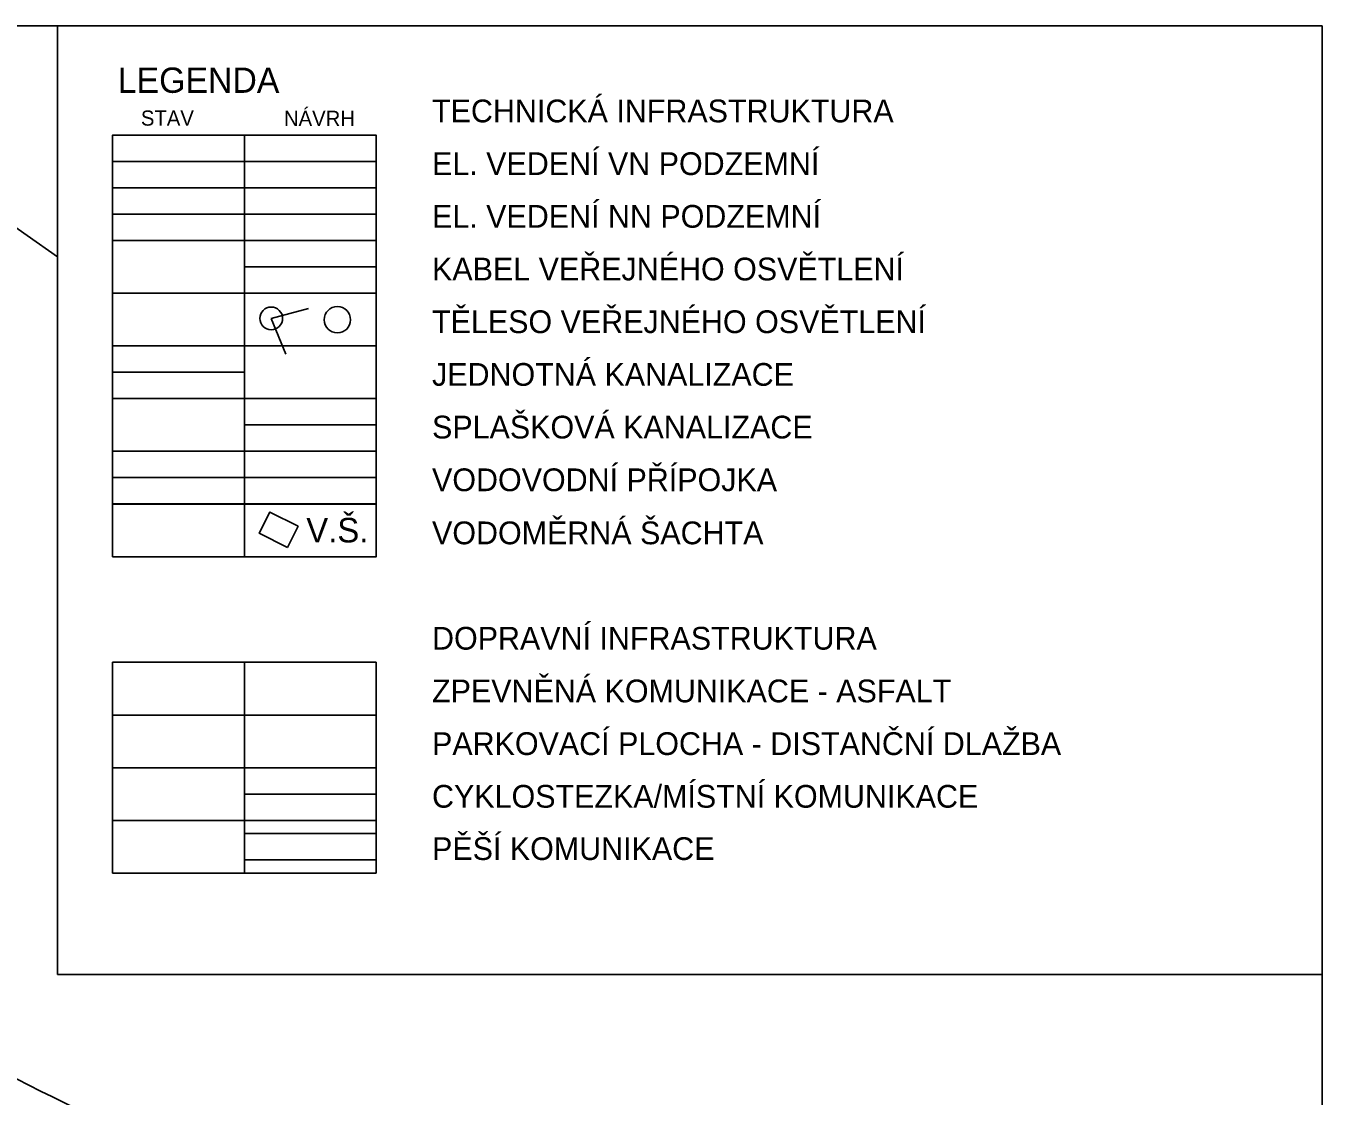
# Model space of a CAD drawing. Extents: x -504998 to -504814, y -1117353 to -1117234.
# Drawn here: x -504875.37 to -504826.17, y -1117277.64 to -1117237.02 of the extents above; entities that cross this region are included whole.
import ezdxf

# ---------------------------------------------------------------- set-up
doc = ezdxf.new("R2010")
doc.units = 0
for name, color, linetype in [('01_ST tenká', 7, 'Continuous'), ('02_PL_PARKOVISTE', 7, 'Continuous'), ('03_razitko', 7, 'Continuous'), ('_01_CYKLOSTEZKA', 7, 'Continuous'), ('_01_kanalizace', 7, 'Continuous'), ('_01_vedeni_NN_nadzemni', 7, 'Continuous'), ('_01_vedeni_VN_podzemni', 7, 'Continuous'), ('_01_vedeni_VN_podzemni_NAVRH', 7, 'Continuous'), ('_01_VO', 7, 'Continuous'), ('_01_vodovod_pripojky', 7, 'Continuous'), ('_02_pl_ cesta', 7, 'Continuous'), ('Hranice parcel', 7, 'Continuous'), ('pop-ram-popis', 7, 'Continuous')]:
    doc.layers.add(name, color=color, linetype=linetype)

msp = doc.modelspace()

# ---------------------------------------------------------------- linework, layer by layer
at = {"layer": '01_ST tenká'}
for p, q in [((-504867.08, -1117267.675), (-504862.08, -1117267.675)), ((-504867.08, -1117267.675), (-504862.08, -1117267.675)), ((-504867.08, -1117268.675), (-504862.08, -1117268.675)), ((-504867.08, -1117268.675), (-504862.08, -1117268.675))]:
    msp.add_line(p, q, dxfattribs=at)
msp.add_open_spline([(-504884.688, -1117272.271), (-504882.067, -1117273.747), (-504872.833, -1117278.571), (-504857.22, -1117285.84), (-504840.071, -1117292.154), (-504829.913, -1117296.084), (-504826.17, -1117297.542)], degree=3, dxfattribs=at)
at = {"layer": '02_PL_PARKOVISTE'}
msp.add_lwpolyline([(-504867.08, -1117265.175), (-504862.08, -1117265.175), (-504862.08, -1117263.175), (-504867.08, -1117263.175)], close=True, dxfattribs=at)
msp.add_lwpolyline([(-504867.08, -1117265.175), (-504862.08, -1117265.175), (-504862.08, -1117263.175), (-504867.08, -1117263.175)], close=True, dxfattribs=at)
at = {"layer": '_01_CYKLOSTEZKA'}
msp.add_line((-504867.08, -1117266.175), (-504862.08, -1117266.175), dxfattribs=at)
msp.add_line((-504867.08, -1117266.175), (-504862.08, -1117266.175), dxfattribs=at)
at = {"layer": '_01_kanalizace'}
for p, q in [((-504872.08, -1117250.16), (-504867.08, -1117250.16)), ((-504872.08, -1117250.16), (-504867.08, -1117250.16)), ((-504867.08, -1117252.16), (-504862.08, -1117252.16)), ((-504867.08, -1117252.16), (-504862.08, -1117252.16))]:
    msp.add_line(p, q, dxfattribs=at)
at = {"layer": '_01_vedeni_NN_nadzemni'}
msp.add_line((-504872.08, -1117244.16), (-504867.08, -1117244.16), dxfattribs=at)
msp.add_line((-504872.08, -1117244.16), (-504867.08, -1117244.16), dxfattribs=at)
at = {"layer": '_01_vedeni_VN_podzemni'}
msp.add_line((-504872.08, -1117242.16), (-504867.08, -1117242.16), dxfattribs=at)
msp.add_line((-504872.08, -1117242.16), (-504867.08, -1117242.16), dxfattribs=at)
at = {"layer": '_01_vedeni_VN_podzemni_NAVRH'}
for p, q in [((-504867.08, -1117242.16), (-504862.08, -1117242.16)), ((-504867.08, -1117242.16), (-504862.08, -1117242.16)), ((-504867.08, -1117244.16), (-504862.08, -1117244.16)), ((-504867.08, -1117244.16), (-504862.08, -1117244.16))]:
    msp.add_line(p, q, dxfattribs=at)
at = {"layer": '_01_VO'}
for p, q in [((-504867.08, -1117246.16), (-504862.08, -1117246.16)), ((-504867.08, -1117246.16), (-504862.08, -1117246.16)), ((-504864.642, -1117247.744), (-504866.06, -1117248.12)), ((-504864.642, -1117247.744), (-504866.06, -1117248.12)), ((-504865.51, -1117249.48), (-504866.06, -1117248.12)), ((-504865.51, -1117249.48), (-504866.06, -1117248.12))]:
    msp.add_line(p, q, dxfattribs=at)
for centre, radius in [((-504866.06, -1117248.12), 0.43), ((-504866.06, -1117248.12), 0.43), ((-504863.55, -1117248.17), 0.5), ((-504863.55, -1117248.17), 0.5)]:
    msp.add_circle(centre, radius, dxfattribs=at)
at = {"layer": '_01_vodovod_pripojky'}
for p, q in [((-504872.08, -1117254.16), (-504867.08, -1117254.16)), ((-504872.08, -1117254.16), (-504867.08, -1117254.16)), ((-504867.08, -1117254.16), (-504862.08, -1117254.16)), ((-504867.08, -1117254.16), (-504862.08, -1117254.16))]:
    msp.add_line(p, q, dxfattribs=at)
msp.add_lwpolyline([(-504865.441, -1117256.812), (-504865.039, -1117256.008), (-504866.112, -1117255.471), (-504866.515, -1117256.276)], close=True, dxfattribs=at)
msp.add_lwpolyline([(-504865.441, -1117256.812), (-504865.039, -1117256.008), (-504866.112, -1117255.471), (-504866.515, -1117256.276)], close=True, dxfattribs=at)
at = {"layer": '_02_pl_ cesta'}
for points in [[(-504867.08, -1117263.175), (-504862.08, -1117263.175), (-504862.08, -1117261.175), (-504867.08, -1117261.175)], [(-504867.08, -1117263.175), (-504862.08, -1117263.175), (-504862.08, -1117261.175), (-504867.08, -1117261.175)], [(-504867.08, -1117267.175), (-504862.08, -1117267.175), (-504862.08, -1117265.175), (-504867.08, -1117265.175)], [(-504867.08, -1117267.175), (-504862.08, -1117267.175), (-504862.08, -1117265.175), (-504867.08, -1117265.175)], [(-504867.08, -1117267.675), (-504862.08, -1117267.675), (-504862.08, -1117268.675), (-504867.08, -1117268.675)], [(-504867.08, -1117267.675), (-504862.08, -1117267.675), (-504862.08, -1117268.675), (-504867.08, -1117268.675)]]:
    msp.add_lwpolyline(points, close=True, dxfattribs=at)
at = {"layer": 'Hranice parcel'}
msp.add_line((-504874.17, -1117245.785), (-504886.671, -1117237.019), dxfattribs=at)
at = {"layer": 'pop-ram-popis'}
for points in [[(-504985.829, -1117237.019), (-504826.17, -1117237.019), (-504826.17, -1117339.419), (-504985.829, -1117339.419)], [(-504826.17, -1117339.419), (-504826.17, -1117273.019), (-504874.17, -1117273.019), (-504874.17, -1117237.019), (-504985.829, -1117237.019), (-504985.829, -1117339.419)], [(-504826.17, -1117339.419), (-504826.17, -1117237.019), (-504985.829, -1117237.019), (-504985.829, -1117339.419)], [(-504826.17, -1117273.019), (-504874.17, -1117273.019), (-504874.17, -1117237.019), (-504985.829, -1117237.019), (-504985.829, -1117339.419), (-504826.17, -1117339.419)], [(-504826.17, -1117237.019), (-504874.17, -1117237.019), (-504874.17, -1117273.019), (-504826.17, -1117273.019)], [(-504826.17, -1117273.019), (-504826.17, -1117237.019), (-504874.17, -1117237.019), (-504874.17, -1117273.019)], [(-504872.08, -1117243.16), (-504867.08, -1117243.16), (-504867.08, -1117241.16), (-504872.08, -1117241.16)], [(-504872.08, -1117243.16), (-504867.08, -1117243.16), (-504867.08, -1117241.16), (-504872.08, -1117241.16)], [(-504867.08, -1117243.16), (-504862.08, -1117243.16), (-504862.08, -1117241.16), (-504867.08, -1117241.16)], [(-504867.08, -1117243.16), (-504862.08, -1117243.16), (-504862.08, -1117241.16), (-504867.08, -1117241.16)], [(-504872.08, -1117245.16), (-504867.08, -1117245.16), (-504867.08, -1117243.16), (-504872.08, -1117243.16)], [(-504872.08, -1117245.16), (-504867.08, -1117245.16), (-504867.08, -1117243.16), (-504872.08, -1117243.16)], [(-504867.08, -1117245.16), (-504862.08, -1117245.16), (-504862.08, -1117243.16), (-504867.08, -1117243.16)], [(-504867.08, -1117245.16), (-504862.08, -1117245.16), (-504862.08, -1117243.16), (-504867.08, -1117243.16)], [(-504872.08, -1117247.16), (-504867.08, -1117247.16), (-504867.08, -1117245.16), (-504872.08, -1117245.16)], [(-504872.08, -1117247.16), (-504867.08, -1117247.16), (-504867.08, -1117245.16), (-504872.08, -1117245.16)], [(-504867.08, -1117247.16), (-504862.08, -1117247.16), (-504862.08, -1117245.16), (-504867.08, -1117245.16)], [(-504867.08, -1117247.16), (-504862.08, -1117247.16), (-504862.08, -1117245.16), (-504867.08, -1117245.16)], [(-504872.08, -1117249.16), (-504867.08, -1117249.16), (-504867.08, -1117247.16), (-504872.08, -1117247.16)], [(-504872.08, -1117249.16), (-504867.08, -1117249.16), (-504867.08, -1117247.16), (-504872.08, -1117247.16)], [(-504867.08, -1117249.16), (-504862.08, -1117249.16), (-504862.08, -1117247.16), (-504867.08, -1117247.16)], [(-504867.08, -1117249.16), (-504862.08, -1117249.16), (-504862.08, -1117247.16), (-504867.08, -1117247.16)], [(-504872.08, -1117251.16), (-504867.08, -1117251.16), (-504867.08, -1117249.16), (-504872.08, -1117249.16)], [(-504872.08, -1117251.16), (-504867.08, -1117251.16), (-504867.08, -1117249.16), (-504872.08, -1117249.16)], [(-504867.08, -1117251.16), (-504862.08, -1117251.16), (-504862.08, -1117249.16), (-504867.08, -1117249.16)], [(-504867.08, -1117251.16), (-504862.08, -1117251.16), (-504862.08, -1117249.16), (-504867.08, -1117249.16)], [(-504872.08, -1117253.16), (-504867.08, -1117253.16), (-504867.08, -1117251.16), (-504872.08, -1117251.16)], [(-504872.08, -1117253.16), (-504867.08, -1117253.16), (-504867.08, -1117251.16), (-504872.08, -1117251.16)], [(-504867.08, -1117253.16), (-504862.08, -1117253.16), (-504862.08, -1117251.16), (-504867.08, -1117251.16)], [(-504867.08, -1117253.16), (-504862.08, -1117253.16), (-504862.08, -1117251.16), (-504867.08, -1117251.16)], [(-504872.08, -1117255.16), (-504867.08, -1117255.16), (-504867.08, -1117253.16), (-504872.08, -1117253.16)], [(-504872.08, -1117255.16), (-504867.08, -1117255.16), (-504867.08, -1117253.16), (-504872.08, -1117253.16)], [(-504867.08, -1117255.16), (-504862.08, -1117255.16), (-504862.08, -1117253.16), (-504867.08, -1117253.16)], [(-504867.08, -1117255.16), (-504862.08, -1117255.16), (-504862.08, -1117253.16), (-504867.08, -1117253.16)], [(-504872.08, -1117257.175), (-504867.08, -1117257.175), (-504867.08, -1117255.175), (-504872.08, -1117255.175)], [(-504872.08, -1117257.175), (-504867.08, -1117257.175), (-504867.08, -1117255.175), (-504872.08, -1117255.175)], [(-504867.08, -1117257.175), (-504862.08, -1117257.175), (-504862.08, -1117255.175), (-504867.08, -1117255.175)], [(-504867.08, -1117257.175), (-504862.08, -1117257.175), (-504862.08, -1117255.175), (-504867.08, -1117255.175)], [(-504872.08, -1117263.175), (-504867.08, -1117263.175), (-504867.08, -1117261.175), (-504872.08, -1117261.175)], [(-504872.08, -1117263.175), (-504867.08, -1117263.175), (-504867.08, -1117261.175), (-504872.08, -1117261.175)], [(-504867.08, -1117263.175), (-504862.08, -1117263.175), (-504862.08, -1117261.175), (-504867.08, -1117261.175)], [(-504867.08, -1117263.175), (-504862.08, -1117263.175), (-504862.08, -1117261.175), (-504867.08, -1117261.175)], [(-504872.08, -1117265.175), (-504867.08, -1117265.175), (-504867.08, -1117263.175), (-504872.08, -1117263.175)], [(-504872.08, -1117265.175), (-504867.08, -1117265.175), (-504867.08, -1117263.175), (-504872.08, -1117263.175)], [(-504867.08, -1117265.175), (-504862.08, -1117265.175), (-504862.08, -1117263.175), (-504867.08, -1117263.175)], [(-504867.08, -1117265.175), (-504862.08, -1117265.175), (-504862.08, -1117263.175), (-504867.08, -1117263.175)], [(-504872.08, -1117267.175), (-504867.08, -1117267.175), (-504867.08, -1117265.175), (-504872.08, -1117265.175)], [(-504872.08, -1117267.175), (-504867.08, -1117267.175), (-504867.08, -1117265.175), (-504872.08, -1117265.175)], [(-504867.08, -1117267.175), (-504862.08, -1117267.175), (-504862.08, -1117265.175), (-504867.08, -1117265.175)], [(-504867.08, -1117267.175), (-504862.08, -1117267.175), (-504862.08, -1117265.175), (-504867.08, -1117265.175)], [(-504872.08, -1117269.175), (-504867.08, -1117269.175), (-504867.08, -1117267.175), (-504872.08, -1117267.175)], [(-504872.08, -1117269.175), (-504867.08, -1117269.175), (-504867.08, -1117267.175), (-504872.08, -1117267.175)], [(-504867.08, -1117269.175), (-504862.08, -1117269.175), (-504862.08, -1117267.175), (-504867.08, -1117267.175)], [(-504867.08, -1117269.175), (-504862.08, -1117269.175), (-504862.08, -1117267.175), (-504867.08, -1117267.175)]]:
    msp.add_lwpolyline(points, close=True, dxfattribs=at)

# ---------------------------------------------------------------- texts
at = {"layer": '03_razitko'}
for s, height, p in [('LEGENDA', 0.96, (-504871.886, -1117239.559)), ('LEGENDA', 0.96, (-504871.886, -1117239.559)), ('TECHNICKÁ INFRASTRUKTURA', 0.864, (-504859.956, -1117240.679)), ('TECHNICKÁ INFRASTRUKTURA', 0.864, (-504859.956, -1117240.679)), ('STAV', 0.576, (-504871.008, -1117240.805)), ('STAV', 0.576, (-504871.008, -1117240.805)), ('NÁVRH', 0.576, (-504865.578, -1117240.815)), ('NÁVRH', 0.576, (-504865.578, -1117240.815)), ('EL. VEDENÍ VN PODZEMNÍ', 0.864, (-504859.956, -1117242.679)), ('EL. VEDENÍ VN PODZEMNÍ', 0.864, (-504859.956, -1117242.679)), ('EL. VEDENÍ NN PODZEMNÍ', 0.864, (-504859.956, -1117244.679)), ('EL. VEDENÍ NN PODZEMNÍ', 0.864, (-504859.956, -1117244.679)), ('KABEL VEŘEJNÉHO OSVĚTLENÍ', 0.864, (-504859.956, -1117246.679)), ('KABEL VEŘEJNÉHO OSVĚTLENÍ', 0.864, (-504859.956, -1117246.679)), ('TĚLESO VEŘEJNÉHO OSVĚTLENÍ', 0.864, (-504859.956, -1117248.679)), ('TĚLESO VEŘEJNÉHO OSVĚTLENÍ', 0.864, (-504859.956, -1117248.679)), ('JEDNOTNÁ KANALIZACE', 0.864, (-504859.956, -1117250.679)), ('JEDNOTNÁ KANALIZACE', 0.864, (-504859.956, -1117250.679)), ('SPLAŠKOVÁ KANALIZACE', 0.864, (-504859.956, -1117252.679)), ('SPLAŠKOVÁ KANALIZACE', 0.864, (-504859.956, -1117252.679)), ('VODOVODNÍ PŘÍPOJKA', 0.864, (-504859.956, -1117254.679)), ('VODOVODNÍ PŘÍPOJKA', 0.864, (-504859.956, -1117254.679)), ('VODOMĚRNÁ ŠACHTA', 0.864, (-504859.956, -1117256.694)), ('VODOMĚRNÁ ŠACHTA', 0.864, (-504859.956, -1117256.694)), ('DOPRAVNÍ INFRASTRUKTURA', 0.864, (-504859.956, -1117260.694)), ('DOPRAVNÍ INFRASTRUKTURA', 0.864, (-504859.956, -1117260.694)), ('ZPEVNĚNÁ KOMUNIKACE - ASFALT', 0.864, (-504859.956, -1117262.694)), ('ZPEVNĚNÁ KOMUNIKACE - ASFALT', 0.864, (-504859.956, -1117262.694)), ('PARKOVACÍ PLOCHA - DISTANČNÍ DLAŽBA', 0.864, (-504859.956, -1117264.694)), ('PARKOVACÍ PLOCHA - DISTANČNÍ DLAŽBA', 0.864, (-504859.956, -1117264.694)), ('CYKLOSTEZKA/MÍSTNÍ KOMUNIKACE', 0.864, (-504859.956, -1117266.694)), ('CYKLOSTEZKA/MÍSTNÍ KOMUNIKACE', 0.864, (-504859.956, -1117266.694)), ('PĚŠÍ KOMUNIKACE', 0.864, (-504859.956, -1117268.679)), ('PĚŠÍ KOMUNIKACE', 0.864, (-504859.956, -1117268.679))]:
    msp.add_text(s, height=height, rotation=360, dxfattribs=at).set_placement(p)
at = {"layer": '_01_vodovod_pripojky'}
msp.add_text('V.Š.', height=0.9331, rotation=359.9846, dxfattribs=at).set_placement((-504864.73, -1117256.625))
msp.add_text('V.Š.', height=0.9331, rotation=359.9846, dxfattribs=at).set_placement((-504864.73, -1117256.625))

doc.saveas('drawing.dxf')
